(* Logix 5000 project; controller Electronic_Displays vendor 1 type 14 code 65 rev 17.4; software revision 17.01; part 7 of 8 *)
(* tags used below, declared in another part *)
   Address : STRING;   // "00" = all signs "01" = address 01 "02" = address 02 etc...(see protocol)
   FileLabel : STRING;   // "A" = default etc...(see protocol)
   ENVariable1Update : BOOL;   // 0 = don't update this variable 1 = update this variable
   Variable1Name : STRING;   // Name of variable Default is = U
   Variable1Value : STRING;   // Actual variable1 value, this need to be text format here.
   ENVariable2Update : BOOL;   // 0 = don't update this variable 1 = update this variable
   Variable2Name : STRING;   // Name of variable Default is = V
   Variable2Value : STRING;   // Actual variable2 value, this need to be text format here.
   ENVariable3Update : BOOL;   // 0 = don't update this variable 1 = update this variable
   Variable3Name : STRING;   // Name of variable Default is = W
   Variable3Value : STRING;   // Actual variable3 value, this need to be text format here.
   ENVariable4Update : BOOL;   // 0 = don't update this variable 1 = update this variable
   Variable4Name : STRING;   // Name of variable Default is = X
   Variable4Value : STRING;   // Actual variable4 value, this need to be text format here.
   EN : BOOL;   // Instruction Interface Enable Bit
   DN : BOOL;   // Instruction Interface Done Bit
   ER : BOOL;   // Instruction Interface Error Bit
   IP : BOOL;   // Instruction Interface InProcess Bit
   map_SignOutput : SINT[496];   // Ethernet/IP LEDSIGN.O Data I/O Mapping
   Packet1Sent : STRING;   // The actual packet sent to the sign (Packet1)
   Packet2Sent : STRING;   // The actual packet sent to the sign (Packet2)
   Packet3Sent : STRING;   // The actual packet sent to the sign (Packet3)
   InCycle : BOOL;   // Incycle
   Error : BOOL;   // Error
   Done : BOOL;   // Done
   SignETX : STRING;   // DO NOT EDIT = ^C
   SignSOH : STRING;   // DO NOT EDIT = ^A
   SignAddress : STRING;
   SignSTX : STRING;   // DO NOT EDIT = ^B
   SignVariable4Name : STRING;
   SignCommandCode : STRING;   // DO NOT EDIT = B
   SignVariable4Value : STRING;
   SignVariable3Value : STRING;
   TotalPacketCount : DINT[7];   // Total Character Count
   Select : DINT;   // Packet Array Select
   PacketMax : DINT;   // Max Packet Count
   Packet3Offset : DINT;
   Packet2Offset : DINT;
   Packet1Offset : DINT;
   Packet : STRING[7];   // Packet Array to send to sign
(* UpdateSignVariables, continued *)

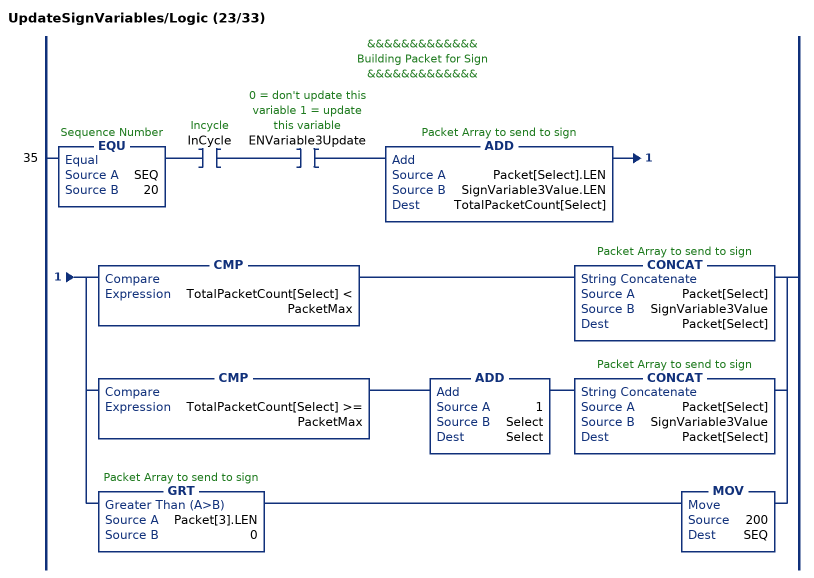
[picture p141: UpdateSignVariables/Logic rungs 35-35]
   // &&&&&&&&&&&&&
   // Building Packet for Sign
   // &&&&&&&&&&&&&
   35: EQU(SEQ,20)XIC(InCycle)XIC(ENVariable3Update)ADD(Packet[Select].LEN,SignVariable3Value.LEN,TotalPacketCount[Select])[CMP(TotalPacketCount[Select] < PacketMax) CONCAT(Packet[Select],SignVariable3Value,Packet[Select]) ,CMP(TotalPacketCount[Select] >= PacketMax) ADD(1,Select,Select) CONCAT(Packet[Select],SignVariable3Value,Packet[Select]) ,GRT(Packet[3].LEN,0) MOV(200,SEQ) ];
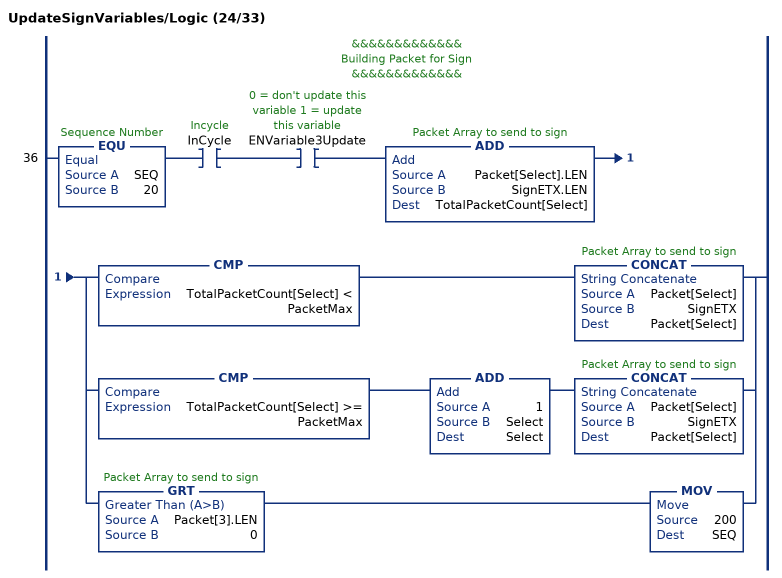
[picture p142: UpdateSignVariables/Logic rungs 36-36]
   // &&&&&&&&&&&&&
   // Building Packet for Sign
   // &&&&&&&&&&&&&
   36: EQU(SEQ,20)XIC(InCycle)XIC(ENVariable3Update)ADD(Packet[Select].LEN,SignETX.LEN,TotalPacketCount[Select])[CMP(TotalPacketCount[Select] < PacketMax) CONCAT(Packet[Select],SignETX,Packet[Select]) ,CMP(TotalPacketCount[Select] >= PacketMax) ADD(1,Select,Select) CONCAT(Packet[Select],SignETX,Packet[Select]) ,GRT(Packet[3].LEN,0) MOV(200,SEQ) ];
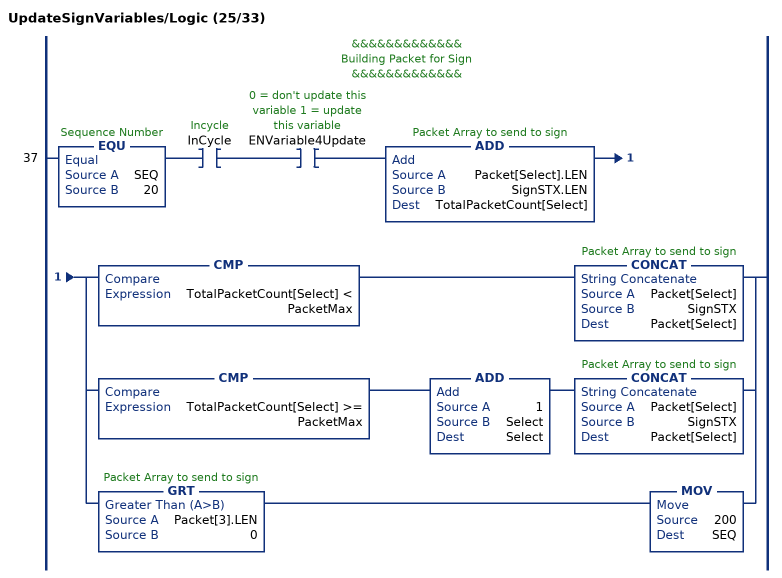
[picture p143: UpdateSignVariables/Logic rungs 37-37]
   // &&&&&&&&&&&&&
   // Building Packet for Sign
   // &&&&&&&&&&&&&
   37: EQU(SEQ,20)XIC(InCycle)XIC(ENVariable4Update)ADD(Packet[Select].LEN,SignSTX.LEN,TotalPacketCount[Select])[CMP(TotalPacketCount[Select] < PacketMax) CONCAT(Packet[Select],SignSTX,Packet[Select]) ,CMP(TotalPacketCount[Select] >= PacketMax) ADD(1,Select,Select) CONCAT(Packet[Select],SignSTX,Packet[Select]) ,GRT(Packet[3].LEN,0) MOV(200,SEQ) ];
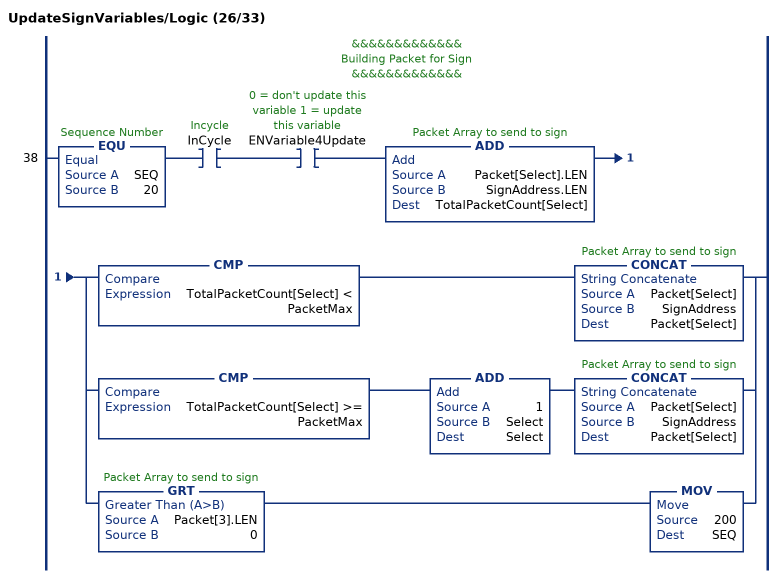
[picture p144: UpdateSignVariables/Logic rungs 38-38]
   // &&&&&&&&&&&&&
   // Building Packet for Sign
   // &&&&&&&&&&&&&
   38: EQU(SEQ,20)XIC(InCycle)XIC(ENVariable4Update)ADD(Packet[Select].LEN,SignAddress.LEN,TotalPacketCount[Select])[CMP(TotalPacketCount[Select] < PacketMax) CONCAT(Packet[Select],SignAddress,Packet[Select]) ,CMP(TotalPacketCount[Select] >= PacketMax) ADD(1,Select,Select) CONCAT(Packet[Select],SignAddress,Packet[Select]) ,GRT(Packet[3].LEN,0) MOV(200,SEQ) ];
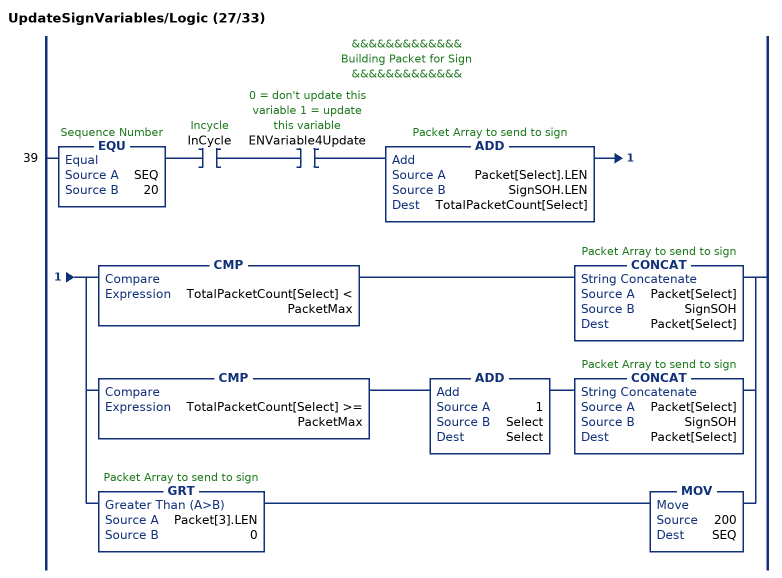
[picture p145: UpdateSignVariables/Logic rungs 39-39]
   // &&&&&&&&&&&&&
   // Building Packet for Sign
   // &&&&&&&&&&&&&
   39: EQU(SEQ,20)XIC(InCycle)XIC(ENVariable4Update)ADD(Packet[Select].LEN,SignSOH.LEN,TotalPacketCount[Select])[CMP(TotalPacketCount[Select] < PacketMax) CONCAT(Packet[Select],SignSOH,Packet[Select]) ,CMP(TotalPacketCount[Select] >= PacketMax) ADD(1,Select,Select) CONCAT(Packet[Select],SignSOH,Packet[Select]) ,GRT(Packet[3].LEN,0) MOV(200,SEQ) ];
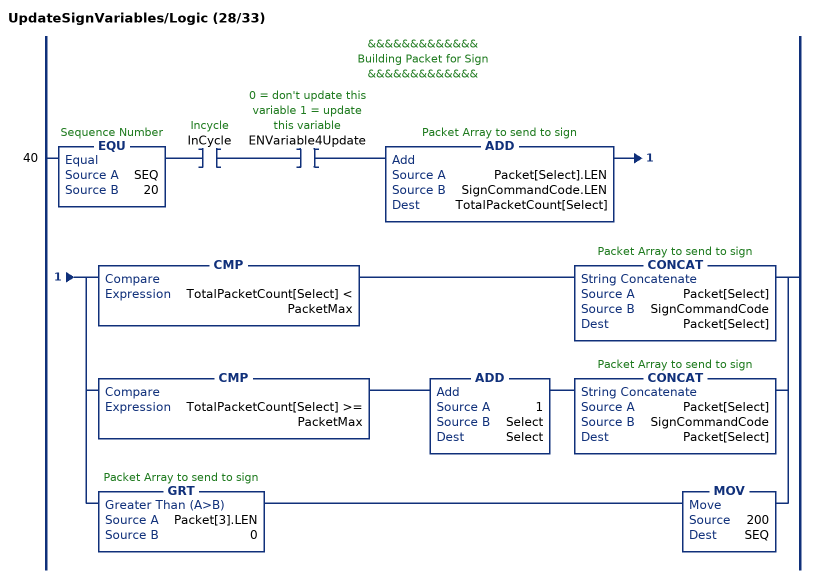
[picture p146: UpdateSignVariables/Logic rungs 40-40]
   // &&&&&&&&&&&&&
   // Building Packet for Sign
   // &&&&&&&&&&&&&
   40: EQU(SEQ,20)XIC(InCycle)XIC(ENVariable4Update)ADD(Packet[Select].LEN,SignCommandCode.LEN,TotalPacketCount[Select])[CMP(TotalPacketCount[Select] < PacketMax) CONCAT(Packet[Select],SignCommandCode,Packet[Select]) ,CMP(TotalPacketCount[Select] >= PacketMax) ADD(1,Select,Select) CONCAT(Packet[Select],SignCommandCode,Packet[Select]) ,GRT(Packet[3].LEN,0) MOV(200,SEQ) ];
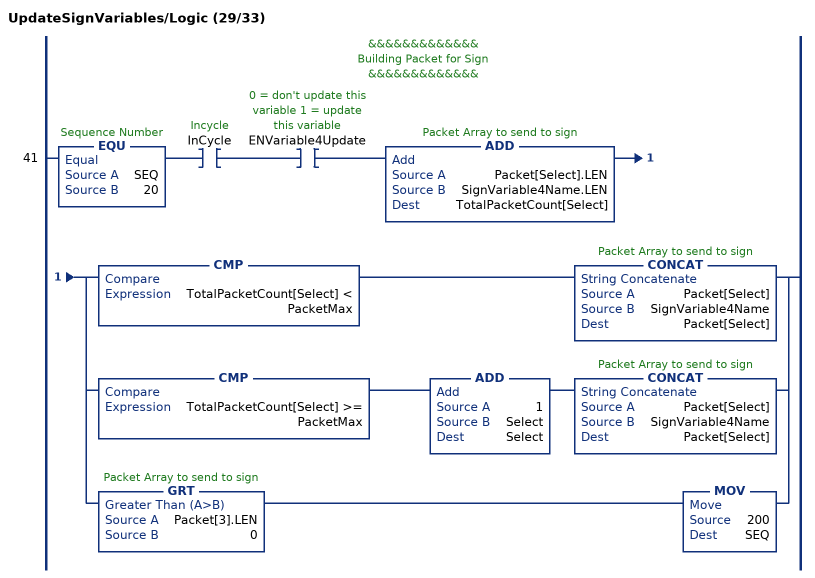
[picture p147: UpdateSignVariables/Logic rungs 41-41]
   // &&&&&&&&&&&&&
   // Building Packet for Sign
   // &&&&&&&&&&&&&
   41: EQU(SEQ,20)XIC(InCycle)XIC(ENVariable4Update)ADD(Packet[Select].LEN,SignVariable4Name.LEN,TotalPacketCount[Select])[CMP(TotalPacketCount[Select] < PacketMax) CONCAT(Packet[Select],SignVariable4Name,Packet[Select]) ,CMP(TotalPacketCount[Select] >= PacketMax) ADD(1,Select,Select) CONCAT(Packet[Select],SignVariable4Name,Packet[Select]) ,GRT(Packet[3].LEN,0) MOV(200,SEQ) ];
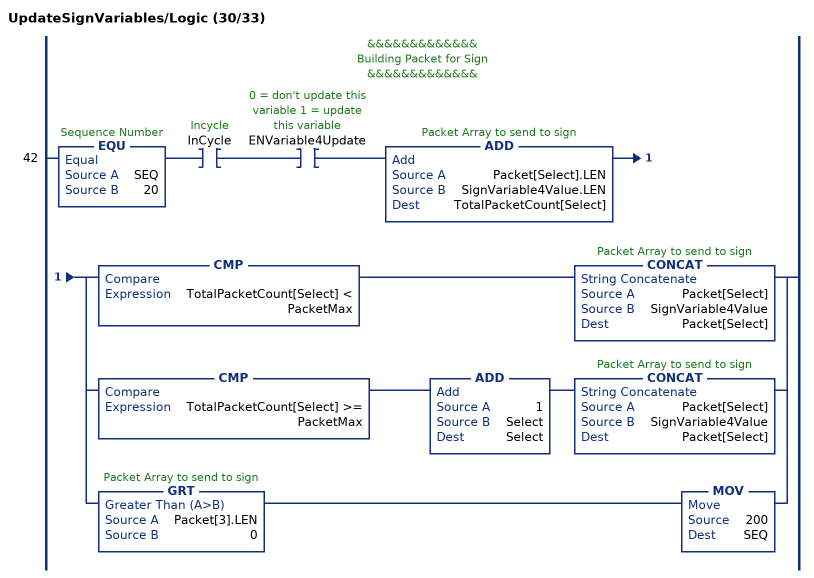
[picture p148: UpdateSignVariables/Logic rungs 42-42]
   // &&&&&&&&&&&&&
   // Building Packet for Sign
   // &&&&&&&&&&&&&
   42: EQU(SEQ,20)XIC(InCycle)XIC(ENVariable4Update)ADD(Packet[Select].LEN,SignVariable4Value.LEN,TotalPacketCount[Select])[CMP(TotalPacketCount[Select] < PacketMax) CONCAT(Packet[Select],SignVariable4Value,Packet[Select]) ,CMP(TotalPacketCount[Select] >= PacketMax) ADD(1,Select,Select) CONCAT(Packet[Select],SignVariable4Value,Packet[Select]) ,GRT(Packet[3].LEN,0) MOV(200,SEQ) ];
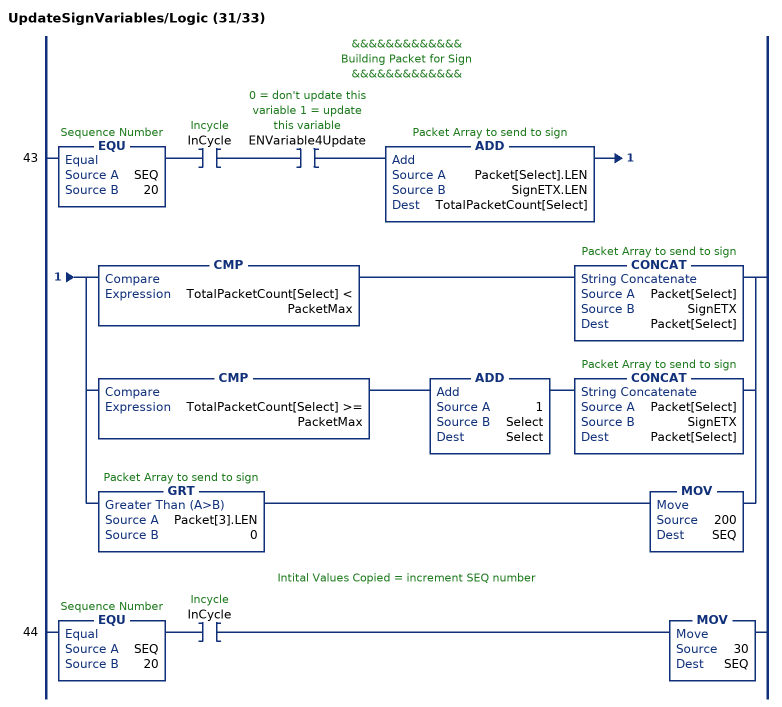
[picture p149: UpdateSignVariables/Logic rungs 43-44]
   // &&&&&&&&&&&&&
   // Building Packet for Sign
   // &&&&&&&&&&&&&
   43: EQU(SEQ,20)XIC(InCycle)XIC(ENVariable4Update)ADD(Packet[Select].LEN,SignETX.LEN,TotalPacketCount[Select])[CMP(TotalPacketCount[Select] < PacketMax) CONCAT(Packet[Select],SignETX,Packet[Select]) ,CMP(TotalPacketCount[Select] >= PacketMax) ADD(1,Select,Select) CONCAT(Packet[Select],SignETX,Packet[Select]) ,GRT(Packet[3].LEN,0) MOV(200,SEQ) ];
   // Intital Values Copied = increment SEQ number
   44: EQU(SEQ,20)XIC(InCycle)MOV(30,SEQ);
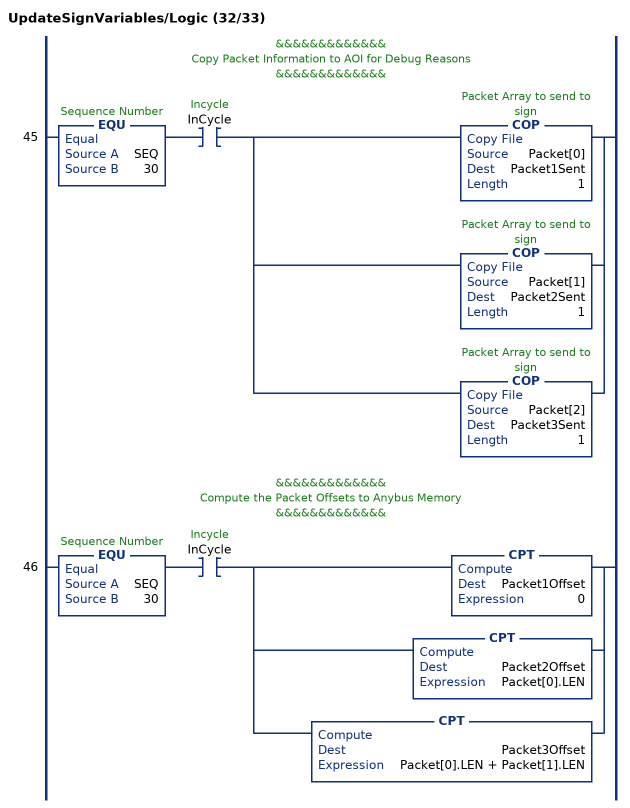
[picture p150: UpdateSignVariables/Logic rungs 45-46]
   // &&&&&&&&&&&&&
   // Copy Packet Information to AOI for Debug Reasons
   // &&&&&&&&&&&&&
   45: EQU(SEQ,30)XIC(InCycle)[COP(Packet[0],Packet1Sent,1) ,COP(Packet[1],Packet2Sent,1) ,COP(Packet[2],Packet3Sent,1) ];
   // &&&&&&&&&&&&&
   // Compute the Packet Offsets to Anybus Memory
   // &&&&&&&&&&&&&
   46: EQU(SEQ,30)XIC(InCycle)[CPT(Packet1Offset,0) ,CPT(Packet2Offset,Packet[0].LEN) ,CPT(Packet3Offset,Packet[0].LEN + Packet[1].LEN) ];
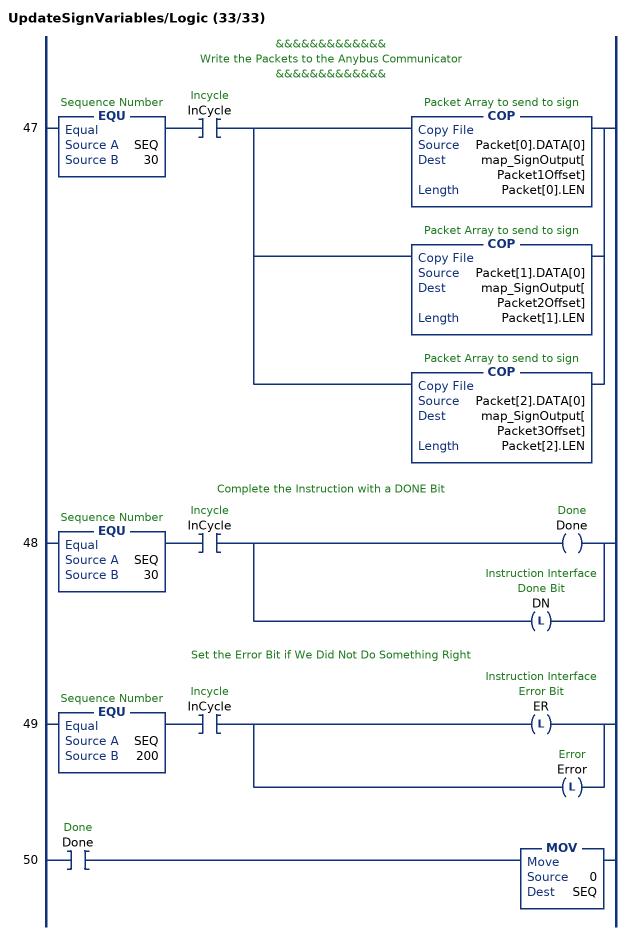
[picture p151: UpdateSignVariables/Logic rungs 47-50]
   // &&&&&&&&&&&&&
   // Write the Packets to the Anybus Communicator
   // &&&&&&&&&&&&&
   47: EQU(SEQ,30)XIC(InCycle)[COP(Packet[0].DATA[0],map_SignOutput[Packet1Offset],Packet[0].LEN) ,COP(Packet[1].DATA[0],map_SignOutput[Packet2Offset],Packet[1].LEN) ,COP(Packet[2].DATA[0],map_SignOutput[Packet3Offset],Packet[2].LEN) ];
   // Complete the Instruction with a DONE Bit
   48: EQU(SEQ,30)XIC(InCycle)[OTE(Done) ,OTL(DN) ];
   // Set the Error Bit if We Did Not Do Something Right
   49: EQU(SEQ,200)XIC(InCycle)[OTL(ER) ,OTL(Error) ];
   50: XIC(Done)MOV(0,SEQ);
END_ROUTINE
END_ADD_ON_INSTRUCTION

VAR_GLOBAL   (* controller tags *)
   ALWAYS_ON : BOOL;
   ColorGreen : STRING := '1';
   ColorRed : STRING := '0';
   Counts_BadParts : DINT := 3;
   Counts_Cycle : STRING := '1.100';
   Counts_GoodParts : DINT := 30;
   Counts_OEE : STRING := '90.90';
   Counts_TotalParts : DINT := 33;
   CycleTime : STRING := '0.08300000';
   CycleTimeReal : REAL := 1.088;
   Delay_Sign01M2 : TIMER := (PRE := 250);
   Delay_Sign02M1 : TIMER := (PRE := 100);
   Down_Cycle : STRING := '0.96';
   DownTime : STRING := '1.70299995';
   DownTimeReal : REAL := 0.885;
   NEVER_ON : BOOL;
   OEE_String : STRING := '90.9090958';
   OEEScore : REAL := 90.909096;
   SEQ : DINT;
   SEQ_TImer : TIMER[20] := ([0].PRE := 7000, [1].PRE := 7000, [2].PRE := 7000, [3].PRE := 7000, [4].PRE := 7000, [5].PRE := 7000);
   Sign01_Erase : ResetSign;
   Sign01_Setup : SetupSignVariables := (ENVariable1Message := 1, ENVariable2Message := 1, ENVariable3Message := 1, ENVariable4Message := 1);
   Sign01_Update : UpdateSignVariables := (ENVariable2Update := 1);
   Sign01M1 : LEDSIGN := (Address := '01', CommandCode := 'D', FileLabel := 'A', Text1Message := 'LINE RUNNING', TextFont := '0', TextColor := '1', TextAlign := 'M', TextAttribute := '5', TextEffect := 'H', TextSpeed := '3', TextPause := '02', Variable1Name := 'U', Variable2Name := 'V', Variable3Name := 'W', Variable4Name := 'X', VariableFont := '0', VariableColor := '2', VariableAttribute := '0', Packet1Sent := '^B01^ADA^F0^O1^GMH^H5LINE RUNNING^C');
   Sign01M2 : LEDSIGN := (Address := '01', CommandCode := 'D', FileLabel := 'A', Text1Message := 'LINE DOWN', Text2Message := 'DOWN TIME ', TextFont := '0', TextColor := '0', TextAlign := 'F', TextAttribute := '5', TextEffect := 'H', TextSpeed := '3', TextPause := '02', Variable1Name := 'U', Variable2Name := 'V', Variable3Name := 'W', Variable4Name := 'X', Variable1Value := '0.62', Variable2Value := '6.88', VariableFont := '0', VariableColor := '2', VariableAttribute := '4', Packet1Sent := '^B01^ABV6.88^C');
   Sign02_Erase : ResetSign;
   Sign02_Setup : SetupSignVariables := (ENVariable1Message := 1, ENVariable2Message := 1, ENVariable3Message := 1, ENVariable4Message := 1);
   Sign02_Update : UpdateSignVariables := (ENVariable1Update := 1, ENVariable2Update := 1, ENVariable3Update := 1, ENVariable4Update := 1);
   Sign02M1 : LEDSIGN := (Address := '02', CommandCode := 'A', FileLabel := 'A', Text1Message := 'Total   ', Text2Message := 'Rejects  ', Text3Message := 'Cycle   ', Text4Message := 'OEE     ', TextFont := '1', TextColor := '1', TextAlign := 'L', TextAttribute := '5', TextEffect := 'H', TextSpeed := '3', TextPause := '02', Variable1Name := 'U', Variable2Name := 'V', Variable3Name := 'W', Variable4Name := 'X', Variable1Value := '22', Variable2Value := '2', Variable3Value := '1.99', Variable4Value := '90.90', VariableFont := '1', VariableColor := '0', VariableAttribute := '4', Packet1Sent := '^B02^AAA^F1^O1^GLH^H5Total   ^F1^O0^H4^NU^M^F1^O1^H5Rejects  ^F1^O0^H4^NV^M^F1^O1', Packet2Sent := '^H5Cycle   ^F1^O0^H4^NW^M^F1^O1^H5OEE     ^F1^O0^H4^NX^C');
   Sign02M2 : LEDSIGN := (Address := '02', CommandCode := 'D', FileLabel := 'A', Text1Message := 'Total ', Text2Message := 'Rejects ', Text3Message := 'Cycle Time   ', Text4Message := 'OEE Score    ', TextFont := '0', TextColor := '1', TextAlign := 'L', TextAttribute := '5', TextEffect := 'H', TextSpeed := '3', TextPause := '02', Variable1Name := 'U', Variable2Name := 'V', Variable3Name := 'W', Variable4Name := 'X', Variable1Value := '321', Variable2Value := '32', Variable3Value := '0.010', Variable4Value := '90.03', VariableFont := '0', VariableColor := '0', VariableAttribute := '4');
   Sign03_Erase : ResetSign;
   Sign03_Setup : SetupSignVariables;
   Sign03M1 : LEDSIGN := (Address := '03', CommandCode := 'D', FileLabel := 'A', Text1Message := 'Ethernet/IP Communication', Text2Message := 'EDV-111', TextFont := '3', TextColor := '2', TextAlign := 'M', TextAttribute := '5', TextEffect := 'D', TextSpeed := '2', TextPause := '02', Variable1Name := 'U', Variable2Name := 'V', Variable3Name := 'W', Variable4Name := 'X', VariableFont := '0', VariableColor := '0', VariableAttribute := '4', Packet1Sent := '^B03^ADA^F3^O2^GMH^H5^ED^I2^J02Ethernet/IP Communication^M^F3^O2^H5EDV-111^C');
   Sign03M2 : LEDSIGN := (Address := '03', CommandCode := 'D', FileLabel := 'A', Text1Message := 'FREE Add-On Instructions                                      for RS Logix 5000', Text3Message := 'CompactLogix and ControlLogix PLCs', TextFont := '0', TextColor := '2', TextAlign := 'F', TextAttribute := '5', TextEffect := 'H', TextSpeed := '3', TextPause := '02', Variable1Name := 'U', Variable2Name := 'V', Variable3Name := 'W', Variable4Name := 'X', Variable1Value := '1738', Variable2Value := '267', Variable3Value := '0.268', Variable4Value := '84.63', VariableFont := '0', VariableColor := '0', VariableAttribute := '4', Packet1Sent := '^B03^ADA^F0^O2^GFH^H5', Packet2Sent := 'FREE Add-On Instructions                                      for RS Logix 5000^M', Packet3Sent := '^F0^O2^H5^M^F0^O2^H5CompactLogix and ControlLogix PLCs^M^F0^O2^H5^C');
   SignTimer01 : TIMER := (PRE := 15000);
   SignTimer02 : TIMER := (PRE := 10000);
   Tag_Sign01M1 : SendSignMessage := (ENText1Message := 1, ENTextFormats := 1);
   Tag_Sign01M2 : SendSignMessage := (ENText1Message := 1, ENText2Message := 1, ENVariable2Message := 1, ENVariableFormats := 1);
   Tag_Sign02M1 : SendSignMessage := (ENText1Message := 1, ENText2Message := 1, ENText3Message := 1, ENText4Message := 1, ENTextFormats := 1, ENVariable1Message := 1, ENVariable2Message := 1, ENVariable3Message := 1, ENVariable4Message := 1, ENVariableFormats := 1, EN := 1, DN := 1);
   Tag_Sign03M1 : SendSignMessage := (ENText1Message := 1, ENText2Message := 1, ENTextFormats := 1, ENTextSpecials := 1);
   Tag_Sign03M2 : SendSignMessage := (ENText1Message := 1, ENText2Message := 1, ENText3Message := 1, ENText4Message := 1, ENTextFormats := 1);
   Time_DownTimer : TIMER := (PRE := 20000);
   Timer_BadParts : TIMER := (PRE := 20000);
   Timer_GoodParts : TIMER := (PRE := 2000);
   Toggle01 : BOOL;
   Toggle02 : BOOL := 1;
   TogglesSign1 : DINT := 1048584;
   TogglesSign2 : DINT := 1048584;
   TogglesSign3 : DINT := 1048584;
   UpdateSign01Timer : TIMER := (PRE := 1000);
END_VAR

PROGRAM MainProgram   (* main routine MainRoutine *)

ROUTINE MainRoutine   (* ladder *)
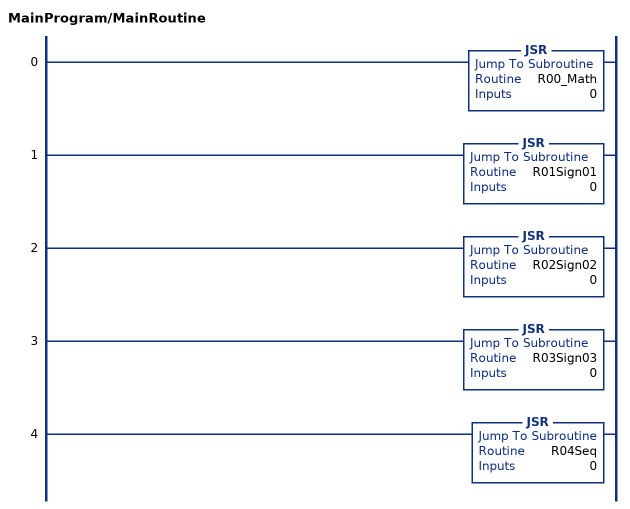
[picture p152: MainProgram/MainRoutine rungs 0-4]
   0: JSR(R00_Math,0);
   1: JSR(R01Sign01,0);
   2: JSR(R02Sign02,0);
   3: JSR(R03Sign03,0);
   4: JSR(R04Seq,0);
END_ROUTINE

ROUTINE R00_Math   (* ladder *)
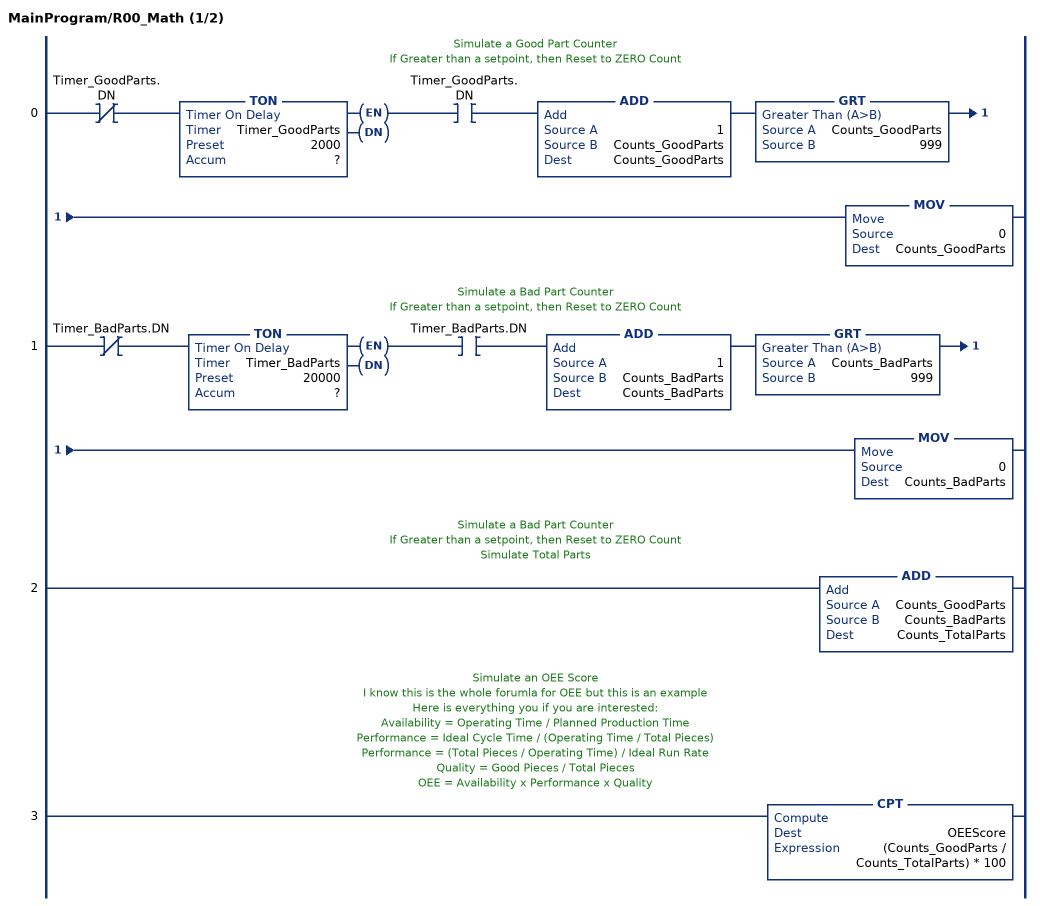
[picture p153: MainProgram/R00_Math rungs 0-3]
   // Simulate a Good Part Counter
   // If Greater than a setpoint, then Reset to ZERO Count
   0: XIO(Timer_GoodParts.DN)TON(Timer_GoodParts,?,?)XIC(Timer_GoodParts.DN)ADD(1,Counts_GoodParts,Counts_GoodParts)GRT(Counts_GoodParts,999)MOV(0,Counts_GoodParts);
   // Simulate a Bad Part Counter
   // If Greater than a setpoint, then Reset to ZERO Count
   1: XIO(Timer_BadParts.DN)TON(Timer_BadParts,?,?)XIC(Timer_BadParts.DN)ADD(1,Counts_BadParts,Counts_BadParts)GRT(Counts_BadParts,999)MOV(0,Counts_BadParts);
   // Simulate a Bad Part Counter
   // If Greater than a setpoint, then Reset to ZERO Count
   // Simulate Total Parts
   2: ADD(Counts_GoodParts,Counts_BadParts,Counts_TotalParts);
   // Simulate an OEE Score
   // I know this is the whole forumla for OEE but this is an example
   // Here is everything you if you are interested:
   // Availability = Operating Time / Planned Production Time
   // Performance = Ideal Cycle Time / (Operating Time / Total Pieces)
   // Performance = (Total Pieces / Operating Time) / Ideal Run Rate
   // Quality = Good Pieces / Total Pieces
   // OEE = Availability x Performance x Quality
   3: CPT(OEEScore,(Counts_GoodParts / Counts_TotalParts) * 100);
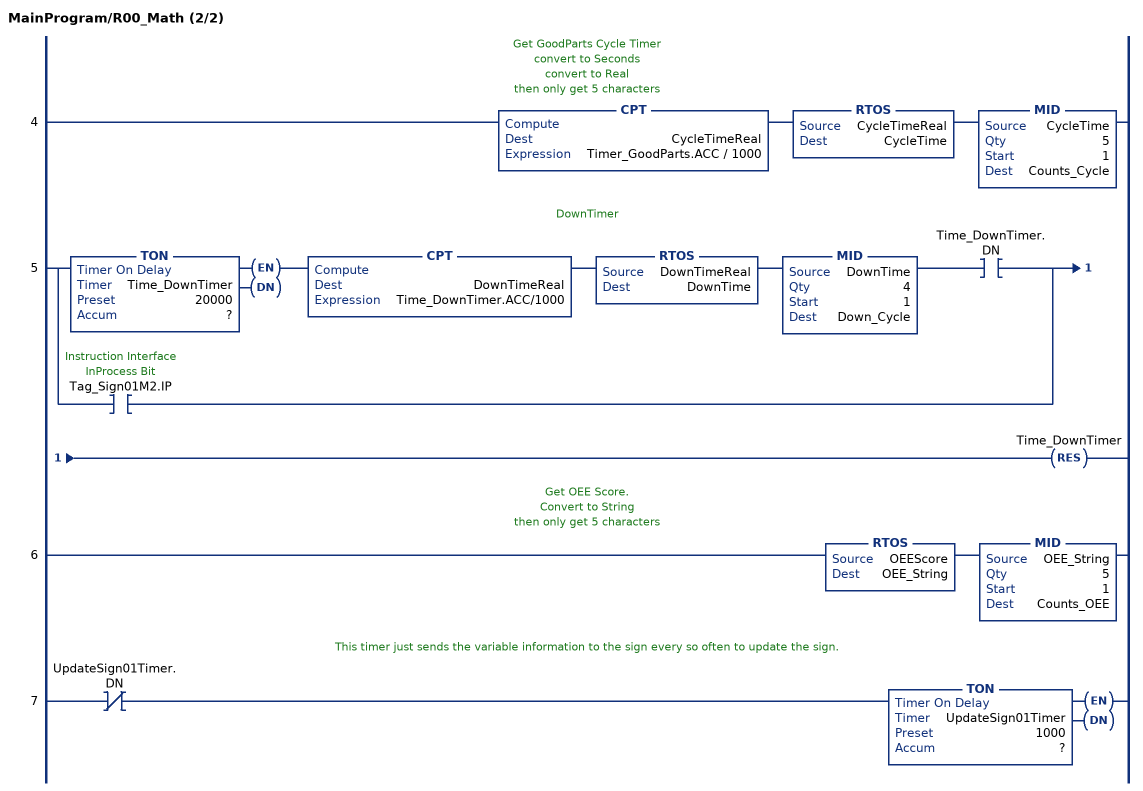
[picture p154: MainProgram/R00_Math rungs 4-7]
   // Get GoodParts Cycle Timer
   // convert to Seconds
   // convert to Real
   // then only get 5 characters
   4: CPT(CycleTimeReal,Timer_GoodParts.ACC / 1000)RTOS(CycleTimeReal,CycleTime)MID(CycleTime,5,1,Counts_Cycle);
   // DownTimer
   5: [TON(Time_DownTimer,?,?) CPT(DownTimeReal,Time_DownTimer.ACC/1000) RTOS(DownTimeReal,DownTime) MID(DownTime,4,1,Down_Cycle) XIC(Time_DownTimer.DN) ,XIC(Tag_Sign01M2.IP) ]RES(Time_DownTimer);
   // Get OEE Score.
   // Convert to String
   // then only get 5 characters
   6: RTOS(OEEScore,OEE_String)MID(OEE_String,5,1,Counts_OEE);
   // This timer just sends the variable information to the sign every so often to update the sign.
   7: XIO(UpdateSign01Timer.DN)TON(UpdateSign01Timer,?,?);
END_ROUTINE

ROUTINE R01Sign01   (* ladder *)
// Sign Address 01
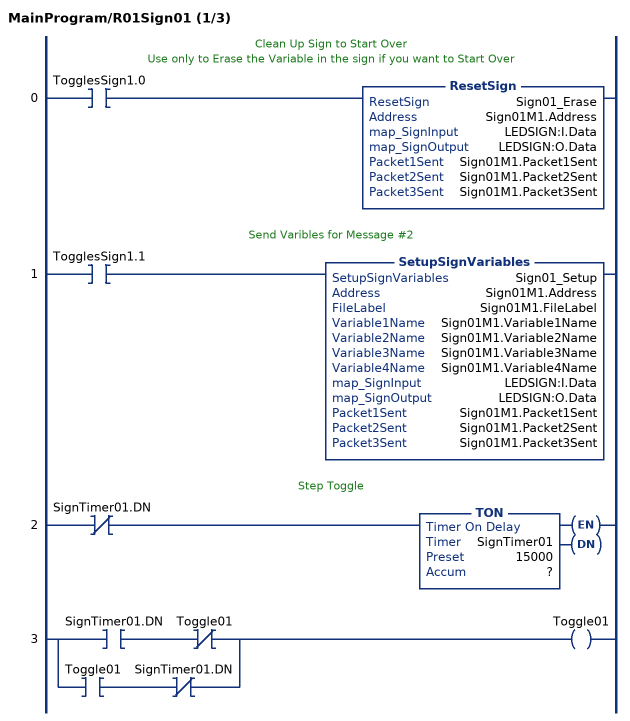
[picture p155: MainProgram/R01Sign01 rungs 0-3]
   // Clean Up Sign to Start Over
   // Use only to Erase the Variable in the sign if you want to Start Over
   0: XIC(TogglesSign1.0)ResetSign(Sign01_Erase,Sign01M1.Address,LEDSIGN:I.Data,LEDSIGN:O.Data,Sign01M1.Packet1Sent,Sign01M1.Packet2Sent,Sign01M1.Packet3Sent);
   // Send Varibles for Message #2
   1: XIC(TogglesSign1.1)SetupSignVariables(Sign01_Setup,Sign01M1.Address,Sign01M1.FileLabel,Sign01M1.Variable1Name,Sign01M1.Variable2Name,Sign01M1.Variable3Name,Sign01M1.Variable4Name,LEDSIGN:I.Data,LEDSIGN:O.Data,Sign01M1.Packet1Sent,Sign01M1.Packet2Sent,Sign01M1.Packet3Sent);
   // Step Toggle
   2: XIO(SignTimer01.DN)TON(SignTimer01,?,?);
   3: [XIC(SignTimer01.DN) XIO(Toggle01) ,XIC(Toggle01) XIO(SignTimer01.DN) ]OTE(Toggle01);
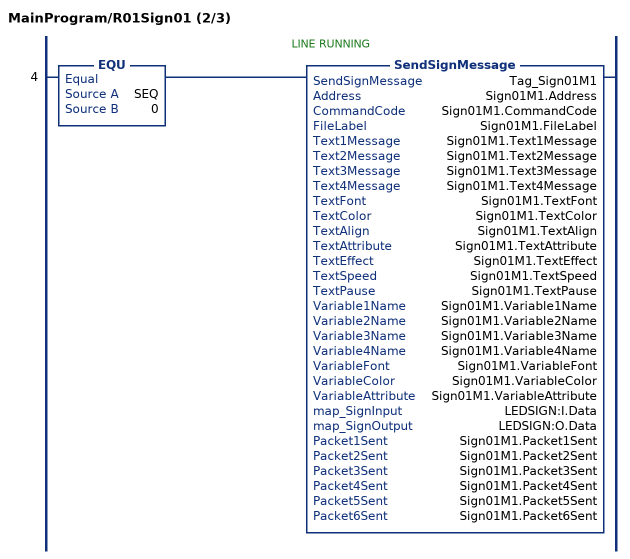
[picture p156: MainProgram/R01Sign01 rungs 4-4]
   // LINE RUNNING
   4: EQU(SEQ,0)SendSignMessage(Tag_Sign01M1,Sign01M1.Address,Sign01M1.CommandCode,Sign01M1.FileLabel,Sign01M1.Text1Message,Sign01M1.Text2Message,Sign01M1.Text3Message,Sign01M1.Text4Message,Sign01M1.TextFont,Sign01M1.TextColor,Sign01M1.TextAlign,Sign01M1.TextAttribute,Sign01M1.TextEffect,Sign01M1.TextSpeed,Sign01M1.TextPause,Sign01M1.Variable1Name,Sign01M1.Variable2Name,Sign01M1.Variable3Name,Sign01M1.Variable4Name,Sign01M1.VariableFont,Sign01M1.VariableColor,Sign01M1.VariableAttribute,LEDSIGN:I.Data,LEDSIGN:O.Data,Sign01M1.Packet1Sent,Sign01M1.Packet2Sent,Sign01M1.Packet3Sent,Sign01M1.Packet4Sent,Sign01M1.Packet5Sent,Sign01M1.Packet6Sent);
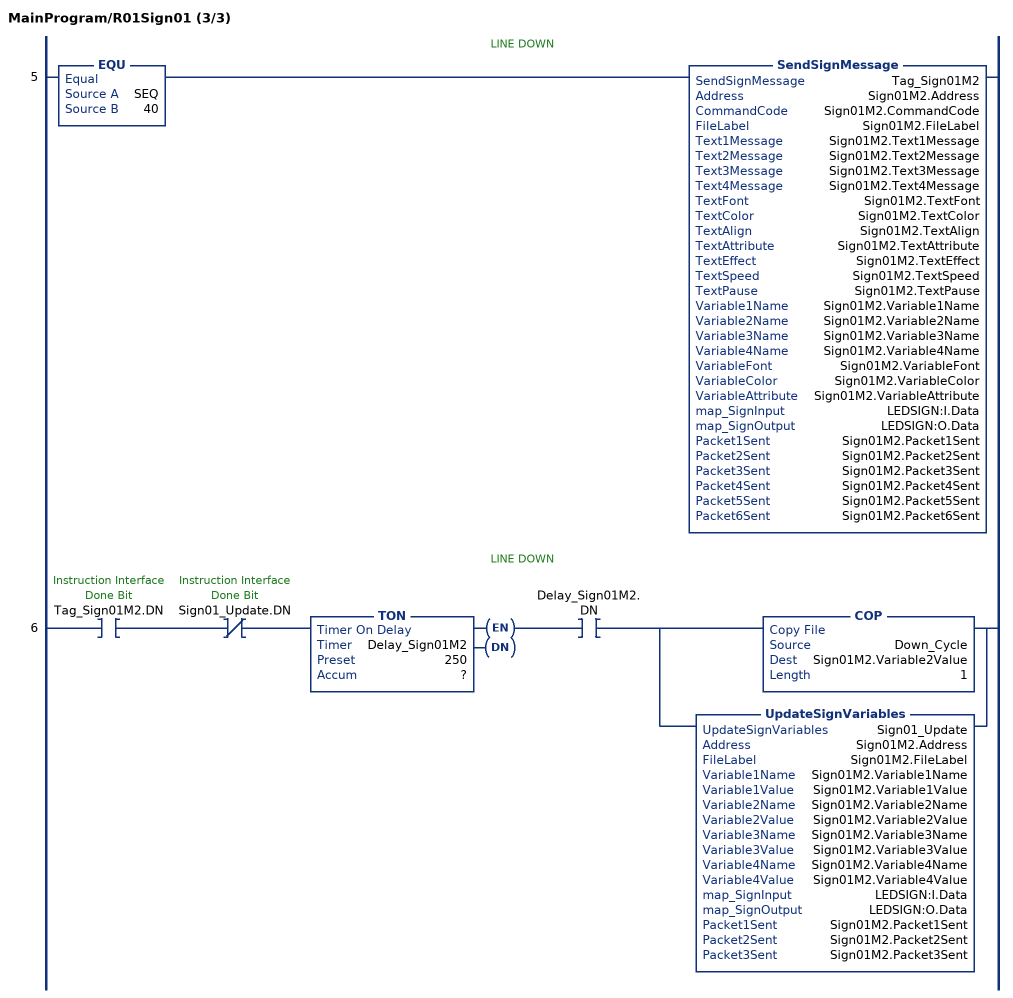
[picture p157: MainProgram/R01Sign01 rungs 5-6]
   // LINE DOWN
   5: EQU(SEQ,40)SendSignMessage(Tag_Sign01M2,Sign01M2.Address,Sign01M2.CommandCode,Sign01M2.FileLabel,Sign01M2.Text1Message,Sign01M2.Text2Message,Sign01M2.Text3Message,Sign01M2.Text4Message,Sign01M2.TextFont,Sign01M2.TextColor,Sign01M2.TextAlign,Sign01M2.TextAttribute,Sign01M2.TextEffect,Sign01M2.TextSpeed,Sign01M2.TextPause,Sign01M2.Variable1Name,Sign01M2.Variable2Name,Sign01M2.Variable3Name,Sign01M2.Variable4Name,Sign01M2.VariableFont,Sign01M2.VariableColor,Sign01M2.VariableAttribute,LEDSIGN:I.Data,LEDSIGN:O.Data,Sign01M2.Packet1Sent,Sign01M2.Packet2Sent,Sign01M2.Packet3Sent,Sign01M2.Packet4Sent,Sign01M2.Packet5Sent,Sign01M2.Packet6Sent);
   // LINE DOWN
   6: XIC(Tag_Sign01M2.DN)XIO(Sign01_Update.DN)TON(Delay_Sign01M2,?,?)XIC(Delay_Sign01M2.DN)[COP(Down_Cycle,Sign01M2.Variable2Value,1) ,UpdateSignVariables(Sign01_Update,Sign01M2.Address,Sign01M2.FileLabel,Sign01M2.Variable1Name,Sign01M2.Variable1Value,Sign01M2.Variable2Name,Sign01M2.Variable2Value,Sign01M2.Variable3Name,Sign01M2.Variable3Value,Sign01M2.Variable4Name,Sign01M2.Variable4Value,LEDSIGN:I.Data,LEDSIGN:O.Data,Sign01M2.Packet1Sent,Sign01M2.Packet2Sent,Sign01M2.Packet3Sent) ];
END_ROUTINE

ROUTINE R02Sign02   (* ladder *)
// Sign Address 02
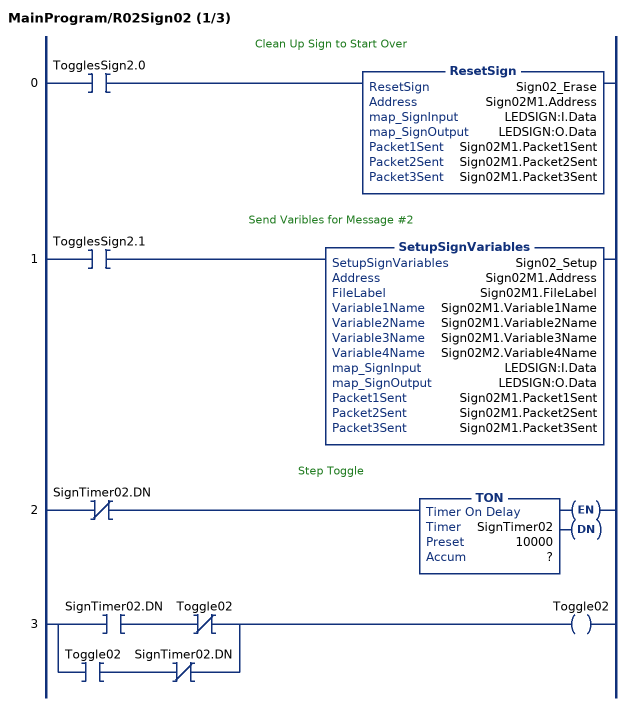
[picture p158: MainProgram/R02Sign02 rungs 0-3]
   // Clean Up Sign to Start Over
   0: XIC(TogglesSign2.0)ResetSign(Sign02_Erase,Sign02M1.Address,LEDSIGN:I.Data,LEDSIGN:O.Data,Sign02M1.Packet1Sent,Sign02M1.Packet2Sent,Sign02M1.Packet3Sent);
   // Send Varibles for Message #2
   1: XIC(TogglesSign2.1)SetupSignVariables(Sign02_Setup,Sign02M1.Address,Sign02M1.FileLabel,Sign02M1.Variable1Name,Sign02M1.Variable2Name,Sign02M1.Variable3Name,Sign02M2.Variable4Name,LEDSIGN:I.Data,LEDSIGN:O.Data,Sign02M1.Packet1Sent,Sign02M1.Packet2Sent,Sign02M1.Packet3Sent);
   // Step Toggle
   2: XIO(SignTimer02.DN)TON(SignTimer02,?,?);
   3: [XIC(SignTimer02.DN) XIO(Toggle02) ,XIC(Toggle02) XIO(SignTimer02.DN) ]OTE(Toggle02);
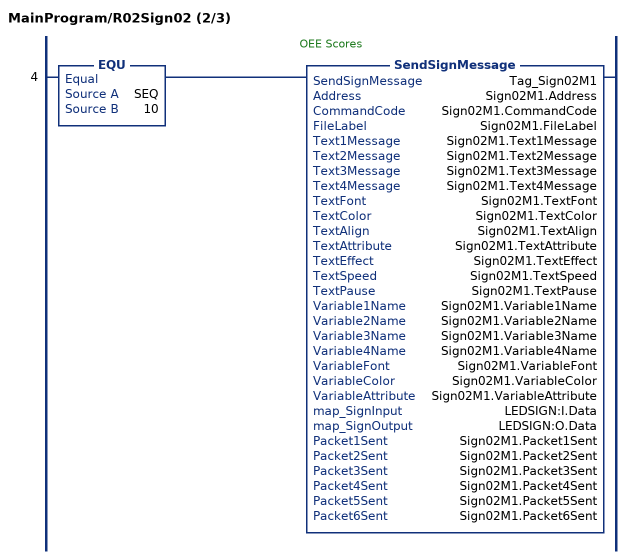
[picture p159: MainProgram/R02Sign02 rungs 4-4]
   // OEE Scores
   4: EQU(SEQ,10)SendSignMessage(Tag_Sign02M1,Sign02M1.Address,Sign02M1.CommandCode,Sign02M1.FileLabel,Sign02M1.Text1Message,Sign02M1.Text2Message,Sign02M1.Text3Message,Sign02M1.Text4Message,Sign02M1.TextFont,Sign02M1.TextColor,Sign02M1.TextAlign,Sign02M1.TextAttribute,Sign02M1.TextEffect,Sign02M1.TextSpeed,Sign02M1.TextPause,Sign02M1.Variable1Name,Sign02M1.Variable2Name,Sign02M1.Variable3Name,Sign02M1.Variable4Name,Sign02M1.VariableFont,Sign02M1.VariableColor,Sign02M1.VariableAttribute,LEDSIGN:I.Data,LEDSIGN:O.Data,Sign02M1.Packet1Sent,Sign02M1.Packet2Sent,Sign02M1.Packet3Sent,Sign02M1.Packet4Sent,Sign02M1.Packet5Sent,Sign02M1.Packet6Sent);
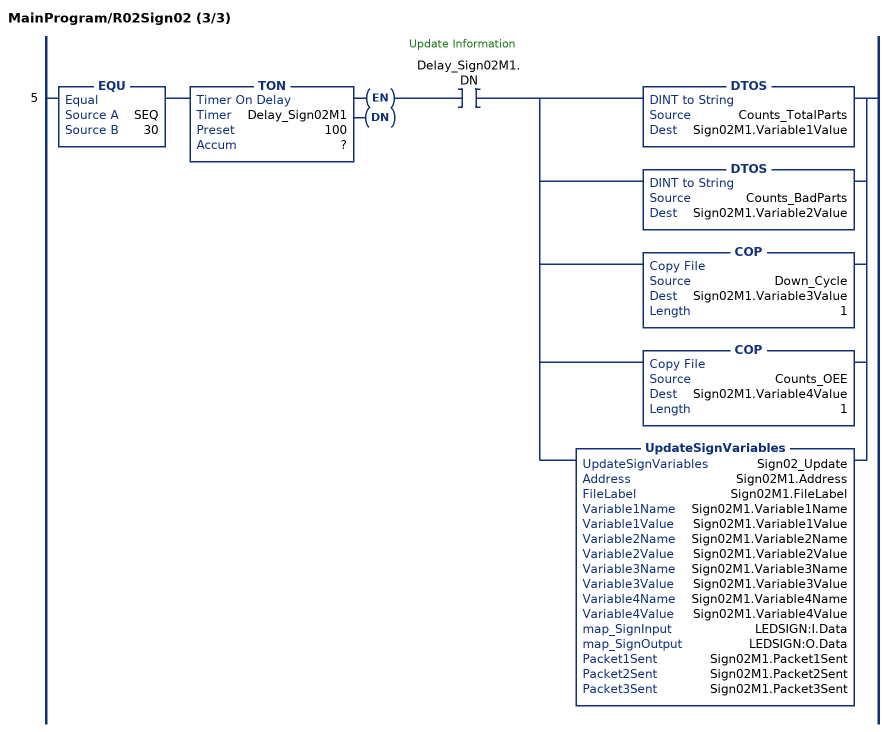
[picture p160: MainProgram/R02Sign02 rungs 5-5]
   // Update Information
   5: EQU(SEQ,30)TON(Delay_Sign02M1,?,?)XIC(Delay_Sign02M1.DN)[DTOS(Counts_TotalParts,Sign02M1.Variable1Value) ,DTOS(Counts_BadParts,Sign02M1.Variable2Value) ,COP(Down_Cycle,Sign02M1.Variable3Value,1) ,COP(Counts_OEE,Sign02M1.Variable4Value,1) ,UpdateSignVariables(Sign02_Update,Sign02M1.Address,Sign02M1.FileLabel,Sign02M1.Variable1Name,Sign02M1.Variable1Value,Sign02M1.Variable2Name,Sign02M1.Variable2Value,Sign02M1.Variable3Name,Sign02M1.Variable3Value,Sign02M1.Variable4Name,Sign02M1.Variable4Value,LEDSIGN:I.Data,LEDSIGN:O.Data,Sign02M1.Packet1Sent,Sign02M1.Packet2Sent,Sign02M1.Packet3Sent) ];
END_ROUTINE
